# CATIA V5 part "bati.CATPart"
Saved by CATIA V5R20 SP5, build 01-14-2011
Part number: bati
Bounding box of the stored display mesh (mm): x -50 to 50, y -130 to 130, z -62 to 120
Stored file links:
  U:\2A\IAO\ThinkMotion\bati.CATPart
  U:\2A\IAO\ThinkMotion\MECANISME 1517.CATProduct
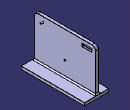
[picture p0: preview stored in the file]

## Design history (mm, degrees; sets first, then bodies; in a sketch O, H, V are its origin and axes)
Set1
  Plane1 "Plan_ref": linked copy from another document
  Point1 to Point4: linked copy from another document
Body1 (main body)
  Sketch1 on Plane1, origin (0, 0, 0), H (0, 1, 0), V (0, 0, 1)
    circle A1 centre (0, 10) radius 3
    point P1 (0, 10)
    reference projected point E1 (0, 10) from Point1
    line L1 (-110, 120) -> (110, 120)
    line L2 (125, 105) -> (125, -50)
    line L3 (125, -50) -> (-125, -50)
    line L4 (-125, -50) -> (-125, 105)
    arc A2 centre (110, 105) radius 15 from (110, 120) to (125, 105) cw
    arc A3 centre (-110, 105) radius 15 from (-110, 120) to (-125, 105) ccw
    reference projected point E2 (0, 0) from Point4
    reference projected point E3 (90, 100) from Point3
    radius A1 = 3
    radius A2 = 15
    radius A3 = 15
    radius A3 = 15 (reference)
    length L3 = 250
    distance E2 L4 = 125 {= Sketch1.length(L3) /2}
    distance L3 L1 = 170
    distance L1 E3 = 20
    coincidence: P1 E1
    horizontal: L1 H, L3 H
    vertical: L2 V, L4 V
    tangency: A2 L1, A2 L2, A3 L1, A3 L4
  Pad1: profile Sketch1, direction (-1, 0, 0), length 12
  Sketch2 on start face of Pad1, origin (0, 0, 0), H (0, 1, 0), V (0, 0, 1)
    circle A1 centre (-90, 100) radius 3
    point P1 (-90, 100)
    reference projected point E1 (-90, 100) from Point2
    radius A1 = 3
    coincidence: P1 E1
  Pad2: profile Sketch2, direction (1, 0, 0), length 10
  Sketch3 on start face of Pad1, origin (0, 0, 0), H (0, 1, 0), V (0, 0, 1)
    line L1 (70, 106) -> (110, 106)
    line L2 (110, 106) -> (110, 94)
    line L3 (110, 94) -> (70, 94)
    line L4 (70, 94) -> (70, 106)
    reference projected point E1 (90, 100) from Point3
    reference projected point E2 (90, 100) from Point3
    reference projected point E3 (90, 100) from Point3
    reference projected point E4 (90, 100) from Point3
    distance L1 E1 = 6
    distance L3 E2 = 6 {= Sketch3.distance(L1 E1)}
    distance E3 L2 = 20
    distance E4 L4 = 20 {= Sketch3.distance(E3 L2)}
    horizontal: L1 H, L3 H
    vertical: L2 V, L4 V
    perpendicularity: L3 L2, L1 L2, L4 L3
  Pocket1: profile Sketch3, direction (-1, 0, 0), length 7
  Sketch4 on face of Pad1 from Sketch1.L3, origin (0, 0, -50), H (1, 0, 0), V (0, -1, 0)
    line L1 (-50, 130) -> (50, 130)
    line L2 (50, 130) -> (50, -130)
    line L3 (50, -130) -> (-50, -130)
    line L4 (-50, -130) -> (-50, 130)
    distance H L1 = 130
    distance H L3 = 130 {= Sketch4.distance(H L1)}
    distance V L2 = 50
    distance V L4 = 50 {= Sketch4.distance(V L2)}
    horizontal: L1 H, L3 H
    vertical: L2 V, L4 V
  Pad3: profile Sketch4, direction (0, 0, -1), length 12
  Fillet1: radius 5, on edge [start face of Pad3 | start face of Pad1]; edge [end face of Pad1 | start face of Pad3]; edge [start face of Pad3 | face of Pad1 from Sketch1.L2]; edge [face of Pad1 from Sketch1.L4 | start face of Pad3]
  Fillet2: radius 0.5, on start face of Pad1; face of Pad2 from Sketch2.A1; edge [face of Pocket1 from Sketch3.L3 | end face of Pocket1]; start face of Pad3; end face of Pad1; end face of Pad3; face of Pad3 from Sketch4.L4; face of Pad3 from Sketch4.L1; face of Pad3 from Sketch4.L3; end face of Pocket1; face of Pocket1 from Sketch3.L2; face of Pocket1 from Sketch3.L4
